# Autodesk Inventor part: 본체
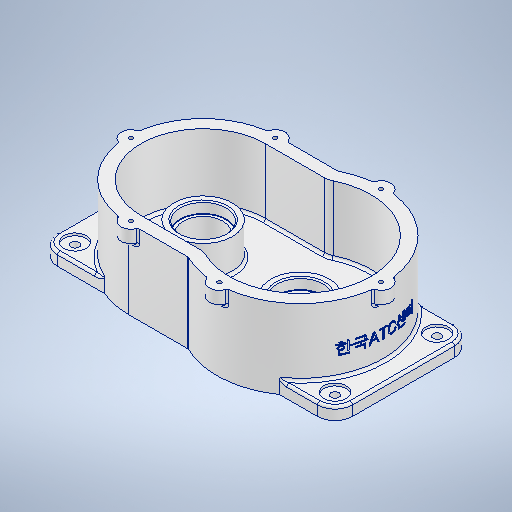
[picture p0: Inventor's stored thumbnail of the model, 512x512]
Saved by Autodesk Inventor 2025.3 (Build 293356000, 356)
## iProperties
Created: 2025-09
Part Number: 본체
Material: 알루미늄 6061
Document SubType Name: Modeling
Designer: PC-15
Mass: 1575.84 g
Surface Area: 1297.91 cm^2
Volume: 583.645 cm^3
Density: 2.7 g/cm^3
Appearance: 알루미늄 - 평지
Author: PC-15
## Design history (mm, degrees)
sketch "스케치1"
  geometry: L1 (118.5, 55)-(-118.5, 55); L2 (-118.5, 55)-(-118.5, -55); L3 (-118.5, -55)-(118.5, -55); L4 (118.5, -55)-(118.5, 55); L5 (118.5, 55)-(-118.5, -55); L6 (-118.5, 55)-(118.5, -55); 1 further point
  constraints: 12 end point, 2 midpoint, 2 parallel, 1 horizontal, 1 perpendicular
  dimensions: "d0" = 237 distance of L3.end L2.end; "d1" = 110 distance of L2.end L1.end
extrude "돌출1" new body sketch "스케치1" distance "d2" = 10; taper "d3" = 0 deg
sketch "스케치2"
  geometry: L1 (-118.5, -55)-(-118.5, 55) reference; L2 (-42.5, 50)-(4.988, 50); L3 (-42.5, -50)-(4.988, -50); L4 (4.988, 60)-(-42.5, 60); L5 (-42.5, -60)-(4.988, -60); L6 (118.5, 55)-(118.5, -55) reference; L7 (-118.5, 55)-(118.5, 55) reference; L8 (-118.5, -55)-(-118.5, 55) reference; L9 (118.5, -55)-(-118.5, -55) reference; A1 r 57 centre (35.5, 0) between (10.654, -51.3) and (10.654, 51.3); A2 r 50 centre (-42.5, 0) between (-42.5, 50) and (-42.5, -50); A3 r 13 centre (4.988, -63) between (10.654, -51.3) and (4.988, -50); A4 r 13 centre (4.988, 63) between (4.988, 50) and (10.654, 51.3); A5 r 3 centre (4.988, 63) between (4.988, 60) and (6.295, 60.3); A6 r 60 centre (-42.5, 0) between (-42.5, 60) and (-42.5, -60); A7 r 3 centre (4.988, -63) between (6.295, -60.3) and (4.988, -60); A8 r 67 centre (35.5, 0) between (6.295, -60.3) and (6.295, 60.3); 7 further points
  constraints: 18 point on circle, 8 centre point, 8 end point, 6 tangent, 2 horizontal, 2 horizontal alignment, 2 point on line, 1 equal radius, 5 other
  dimensions: "d4" = 114 diameter of A1; "d5" = 100 diameter of A2; "d7" = 76 distance from line of L1 A2.centre; "d8" = 78 distance of A1.centre A2.centre; "d9" = 13 radius of A3; "d12" = 10 radial gap between concentric circles of A1 A8
extrude "돌출4" join sketch "스케치2" distance "d15" = 64; taper "d16" = 0 deg
sketch "스케치3"
  geometry: C1 r 23.5 at (35.5, 0); C2 r 23.5 at (-42.5, 0); A1 r 57 centre (35.5, 0) between (10.654, -51.3) and (10.654, 51.3) reference; A2 r 50 centre (-42.5, 0) between (-42.5, 50) and (-42.5, -50) reference; 3 further points
  constraints: 2 centre point, 2 concentric
  dimensions: "d17" = 47 diameter of C1; "d18" = 47 diameter of C2
extrude "돌출5" join sketch "스케치3" distance "d19" = 12; taper "d20" = 0 deg
extrude "돌출6" join sketch "스케치3" distance "d21" = 26; taper "d22" = 0 deg
sketch "스케치4"
  geometry: C1 r 18.5 at (0, 0); C2 r 23.5 at (0, 0) reference; 1 further point
  constraints: 1 centre point, 1 concentric
  dimensions: "d23" = 37 diameter of C1
extrude "돌출7" cut sketch "스케치4" distance "d24" = 9; taper "d25" = 0 deg
sketch "스케치5"
  geometry: C1 r 16 at (0, 0); C2 r 18.5 at (0, 0) reference; 1 further point
  constraints: 1 centre point, 1 concentric
  dimensions: "d26" = 32 diameter of C1
extrude "돌출8" cut sketch "스케치5" distance "d27" = 16; taper "d28" = 0 deg
sketch "스케치6"
  geometry: C1 r 14 at (0, 0); C2 r 16 at (0, 0) reference; 1 further point
  constraints: 1 centre point, 1 concentric
  dimensions: "d29" = 28 diameter of C1
extrude "돌출9" cut sketch "스케치6" distance "d30" = 3; taper "d31" = 0 deg
sketch "스케치7"
  geometry: C1 r 18.5 at (0, 0); C2 r 23.5 at (0, 0) reference; 1 further point
  constraints: 1 centre point, 1 concentric
  dimensions: "d32" = 37 diameter of C1
extrude "돌출10" cut sketch "스케치7" distance "d33" = 9; taper "d34" = 0 deg
sketch "스케치8"
  geometry: C1 r 23.5 at (35.5, 0) reference; C2 r 17.5 at (35.5, 0); 1 further point
  constraints: 1 centre point, 1 coincident
  dimensions: "d35" = 35 diameter of C2
extrude "돌출11" cut sketch "스케치8" distance "d36" = 9.1; taper "d37" = 0 deg
sketch "스케치9"
  geometry: C1 r 15 at (0, 0); C2 r 18.5 at (0, 0) reference; 1 further point
  constraints: 1 centre point, 1 concentric
  dimensions: "d38" = 30 diameter of C1
extrude "돌출12" cut sketch "스케치9" extent not by distance; stored distance "d39" = 9.1; taper "d40" = 0 deg
sketch "스케치10"
  geometry: L1 (-118.5, 55)-(-118.5, -55) reference; L2 (0, 93.8)-(0, -93.8) reference; L3 (-165.9, 0)-(165.9, 0) reference; 5 further points
  constraints: 3 symmetric about line
  dimensions: "d48" = 14 distance from line of L1 point (-104.5, 41); "d49" = 82 distance of point (-104.5, -41) point (-104.5, 41)
hole "구멍1" sketch "스케치10" at (-104.5, 41), (-104.5, -41), (104.5, 41), (104.5, -41) diameter "d41" = 6.6; stored, may be unused: countersink angle "d45" = 90 deg, drill point angle "d47" = 0 deg; dims "d42" = 6, "d43" = 18, "d44" = 2, "d46" = 10
sketch "스케치11"
  geometry: L1 (50.467, -55)-(20.533, -55) reference; L2 (20.533, 55)-(50.467, 55) reference; A1 r 57 centre (35.5, 0) between (20.533, -55) and (50.467, -55) reference; A2 r 57 centre (35.5, 0) between (50.467, 55) and (20.533, 55) reference; 1 further point
extrude "돌출13" join sketch "스케치11" distance "d50" = 10; taper "d51" = 0 deg
sketch "스케치12"
  geometry: L1 (-165.9, 0)-(165.9, 0) reference; C1 r 8 at (-42.5, 58); C2 r 8 at (35.5, 65); C3 r 8 at (35.5, -65); C4 r 8 at (-42.5, -58); C5 r 8 at (-100.5, 0); C6 r 8 at (100.5, 0); C7 r 23.5 at (-42.5, 0) reference; C8 r 23.5 at (35.5, 0) reference; 1 further point
  constraints: 6 centre point, 5 equal radius, 4 vertical alignment, 2 horizontal alignment, 2 other
  dimensions: "d52" = 16 diameter of C1; "d53" = 116 distance of C4.centre C1.centre; "d54" = 130 distance of C3.centre C2.centre; "d55" = 58 distance of C7.centre C5.centre; "d56" = 65 distance of C8.centre C6.centre
extrude "돌출14" join sketch "스케치12" distance "d57" = 12; taper "d58" = 0 deg
sketch "스케치13"
  geometry: L1 (0, 107.408)-(0, -107.408) reference; L2 (-165.9, 0)-(165.9, 0) reference; L3 (-34.754, -60)-(4.988, -60) reference; L4 (4.988, 60)-(-34.754, 60) reference; L5 (4.988, -50)-(-42.5, -50) reference; L6 (-42.5, 50)-(4.988, 50) reference; A1 r 60 centre (-42.5, 0) between (-101.983, -7.861) and (-50.361, -59.483) reference; A2 r 8 centre (-42.5, -58) between (-50.361, -59.483) and (-34.754, -60) reference; A3 r 3 centre (4.988, -63) between (6.295, -60.3) and (4.988, -60) reference; A4 r 67 centre (35.5, 0) between (6.295, -60.3) and (27.649, -66.538) reference; A5 r 8 centre (35.5, -65) between (27.649, -66.538) and (43.351, -66.538) reference; A6 r 67 centre (35.5, 0) between (43.351, -66.538) and (102.038, -7.851) reference; A7 r 8 centre (100.5, 0) between (102.038, -7.851) and (102.038, 7.851) reference; A8 r 67 centre (35.5, 0) between (102.038, 7.851) and (43.351, 66.538) reference; A9 r 8 centre (35.5, 65) between (43.351, 66.538) and (27.649, 66.538) reference; A10 r 67 centre (35.5, 0) between (27.649, 66.538) and (6.295, 60.3) reference; A11 r 3 centre (4.988, 63) between (4.988, 60) and (6.295, 60.3) reference; A12 r 8 centre (-42.5, 58) between (-34.754, 60) and (-50.361, 59.483) reference; A13 r 60 centre (-42.5, 0) between (-50.361, 59.483) and (-101.983, 7.861) reference; A14 r 8 centre (-100.5, 0) between (-101.983, 7.861) and (-101.983, -7.861) reference; A15 r 57 centre (35.5, 0) between (10.654, -51.3) and (10.654, 51.3) reference; A16 r 13 centre (4.988, -63) between (10.654, -51.3) and (4.988, -50) reference; A17 r 50 centre (-42.5, 0) between (-42.5, 50) and (-42.5, -50) reference; A18 r 13 centre (4.988, 63) between (4.988, 50) and (10.654, 51.3) reference; 7 further points
  constraints: 3 coincident, 3 symmetric about line
hole "구멍2" sketch "스케치13" at (35.5, 65), (-42.5, 58), (-100.5, 0), (-42.5, -58), (35.5, -65), (100.5, 0) diameter "d59" = 3.242; stored, may be unused: countersink angle "d63" = 90 deg, drill point angle "d65" = 118 deg; dims "d60" = 8, "d61" = 18, "d62" = 2, "d64" = 10
fillet "모깎기1" dims "d66" = 14
chamfer "모따기2" distance "d70" = 0.3; stored, may be unused: second distance "d71" = 2, angle "d72" = 45 deg
chamfer "모따기3" distance "d73" = 0.8; stored, may be unused: second distance "d74" = 2, angle "d75" = 45 deg
chamfer "모따기4" distance "d76" = 1; stored, may be unused: second distance "d77" = 2, angle "d78" = 45 deg
fillet "모깎기3" dims "d80" = 2
fillet "모깎기4" dims "d81" = 2
fillet "모깎기5" dims "d82" = 2
node "작업 평면1"
sketch "스케치14"
  geometry: L1 (0, 41)-(0, -41) reference; 2 further points
  constraints: 1 horizontal alignment, 1 other
  dimensions: "d84" = 30 distance from line of L1 point (30, 0)
feature "엠보싱1" sketch "스케치14" dims "d0" = 237, "d1" = 110, "d85" = 0.5, "d86" = 0
chamfer "모따기5" distance "d87" = 1; stored, may be unused: second distance "d88" = 2, angle "d89" = 45 deg
node "솔리드1"
node "투영된 루프1"
node "투영된 루프2"
feature "A9D066F2-1C7D-4E18-AEED-F7BC21143FA4" dims "d41" = 6.6, "d42" = 6, "d43" = 18, "d44" = 2, "d45" = 90 deg, "d46" = 10, "d47" = 0
other parameters: "d83" = 169.25
